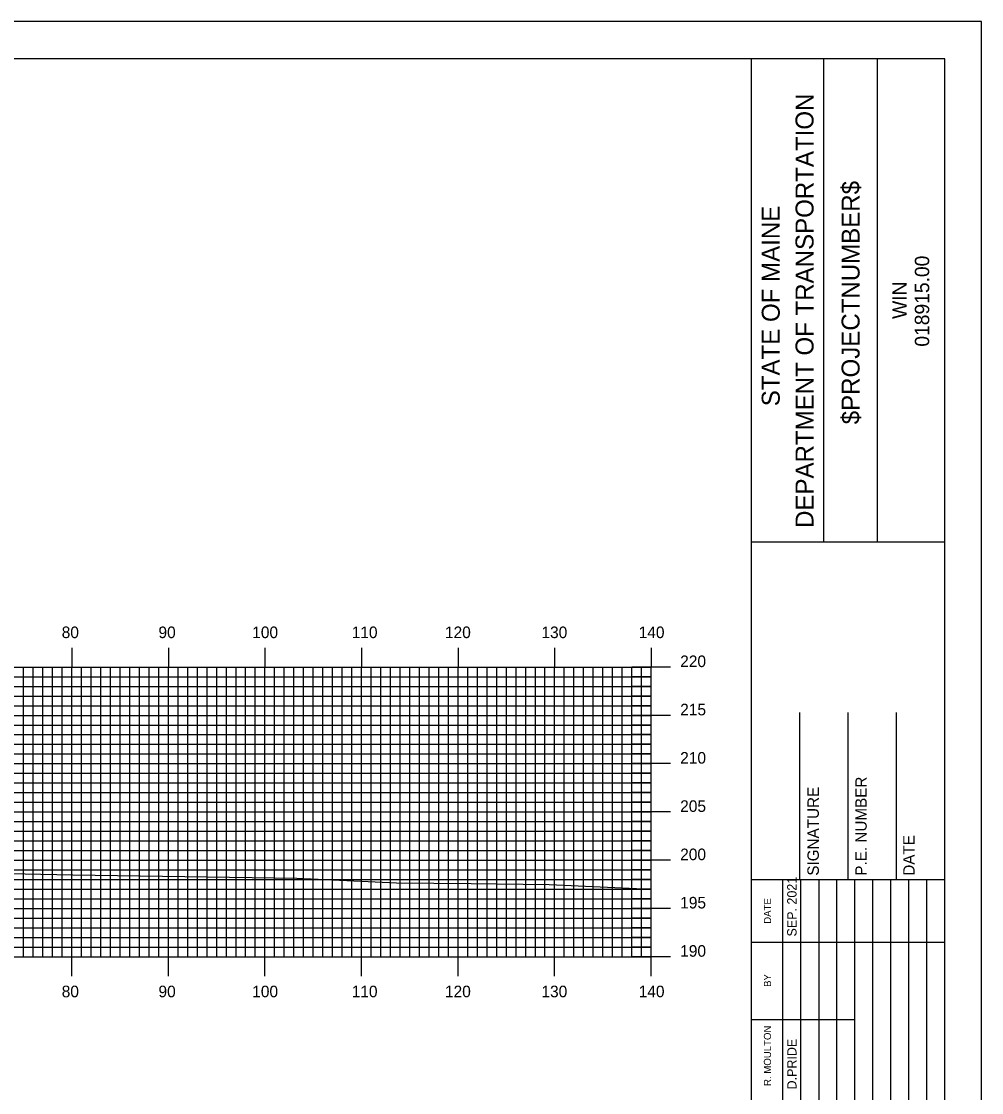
# Model space of a CAD drawing. Extents: x 1805864 to 1806208, y 442591 to 442811.
# Drawn here: x 1806105 to 1806204.4, y 442699.6 to 442810.5 of the extents above; entities that cross this region are included whole.
import ezdxf

# ---------------------------------------------------------------- set-up
doc = ezdxf.new("R2010")
doc.units = 0
for name, color, linetype in [('BORDER', 7, 'Continuous'), ('H_V ANNOTATION', 7, 'Continuous'), ('MAJOR', 7, 'Continuous'), ('MINOR', 7, 'Continuous'), ('PLOT BOUNDARY', 7, 'Continuous'), ('S_Roadway_Centerline', 7, 'Continuous')]:
    doc.layers.add(name, color=color, linetype=linetype)

msp = doc.modelspace()

# ---------------------------------------------------------------- linework, layer by layer
at = {"layer": 'BORDER'}
for p, q in [((1806180.62, 442596.67), (1806180.62, 442806.67)), ((1806188.08, 442756.66), (1806188.08, 442806.66)), ((1806193.67, 442756.66), (1806193.67, 442806.66)), ((1806180.62, 442756.65), (1806200.62, 442756.65)), ((1806185.62, 442721.67), (1806185.62, 442738.97)), ((1806190.62, 442721.67), (1806190.62, 442738.97)), ((1806195.62, 442721.67), (1806195.62, 442738.97)), ((1806180.62, 442721.67), (1806200.62, 442721.67))]:
    msp.add_line(p, q, dxfattribs=at)
msp.add_lwpolyline([(1805880.62, 442596.67), (1806200.62, 442596.67), (1806200.62, 442806.67), (1805880.62, 442806.67)], close=True, dxfattribs=at)
for points in [[(1806183.85, 442715.17), (1806183.85, 442721.67)], [(1806185.71, 442686.68), (1806185.71, 442721.67)], [(1806187.58, 442721.67), (1806187.58, 442686.68)], [(1806189.44, 442686.68), (1806189.44, 442721.67)], [(1806191.3, 442686.68), (1806191.3, 442721.67)], [(1806193.17, 442686.68), (1806193.17, 442721.67)], [(1806195.03, 442686.68), (1806195.03, 442721.67)], [(1806196.89, 442686.68), (1806196.89, 442721.67)], [(1806198.76, 442686.68), (1806198.76, 442721.67)], [(1806183.85, 442686.68), (1806183.85, 442720.26)], [(1806180.62, 442715.17), (1806200.62, 442715.17)], [(1806180.62, 442707.17), (1806183.85, 442707.17)], [(1806183.85, 442707.17), (1806191.3, 442707.17)]]:
    msp.add_lwpolyline(points, dxfattribs=at)
at = {"layer": 'MAJOR'}
for p, q in [((1806110.22, 442745.67), (1806110.22, 442743.67)), ((1806120.22, 442745.67), (1806120.22, 442743.67)), ((1806130.22, 442745.67), (1806130.22, 442743.67)), ((1806140.22, 442745.67), (1806140.22, 442743.67)), ((1806150.22, 442745.67), (1806150.22, 442743.67)), ((1806160.22, 442745.67), (1806160.22, 442743.67)), ((1806170.22, 442745.67), (1806170.22, 442743.67)), ((1805890.22, 442743.67), (1806170.22, 442743.67)), ((1805890.22, 442743.67), (1806170.22, 442743.67)), ((1806110.22, 442713.67), (1806110.22, 442743.67)), ((1806120.22, 442713.67), (1806120.22, 442743.67)), ((1806130.22, 442713.67), (1806130.22, 442743.67)), ((1806140.22, 442713.67), (1806140.22, 442743.67)), ((1806150.22, 442713.67), (1806150.22, 442743.67)), ((1806160.22, 442713.67), (1806160.22, 442743.67)), ((1806172.22, 442743.67), (1806168.22, 442743.67)), ((1806170.22, 442713.67), (1806170.22, 442743.67)), ((1806170.22, 442713.67), (1806170.22, 442743.67)), ((1805890.22, 442738.67), (1806170.22, 442738.67)), ((1806172.22, 442738.67), (1806168.22, 442738.67)), ((1805890.22, 442733.67), (1806170.22, 442733.67)), ((1806172.22, 442733.67), (1806168.22, 442733.67)), ((1805890.22, 442728.67), (1806170.22, 442728.67)), ((1806172.22, 442728.67), (1806168.22, 442728.67)), ((1805890.22, 442723.67), (1806170.22, 442723.67)), ((1806172.22, 442723.67), (1806168.22, 442723.67)), ((1805890.22, 442718.67), (1806170.22, 442718.67)), ((1806172.22, 442718.67), (1806168.22, 442718.67)), ((1805890.22, 442713.67), (1806170.22, 442713.67)), ((1805890.22, 442713.67), (1806170.22, 442713.67)), ((1806110.22, 442711.66), (1806110.22, 442713.67)), ((1806120.22, 442711.66), (1806120.22, 442713.67)), ((1806130.22, 442711.66), (1806130.22, 442713.67)), ((1806140.22, 442711.66), (1806140.22, 442713.67)), ((1806150.22, 442711.66), (1806150.22, 442713.67)), ((1806160.22, 442711.66), (1806160.22, 442713.67)), ((1806172.22, 442713.67), (1806168.22, 442713.67)), ((1806170.22, 442711.66), (1806170.22, 442713.67))]:
    msp.add_line(p, q, dxfattribs=at)
at = {"layer": 'MINOR'}
for p, q in [((1806105.22, 442713.67), (1806105.22, 442743.67)), ((1806106.22, 442713.67), (1806106.22, 442743.67)), ((1806107.22, 442713.67), (1806107.22, 442743.67)), ((1806108.22, 442713.67), (1806108.22, 442743.67)), ((1806109.22, 442713.67), (1806109.22, 442743.67)), ((1806111.22, 442713.67), (1806111.22, 442743.67)), ((1806112.22, 442713.67), (1806112.22, 442743.67)), ((1806113.22, 442713.67), (1806113.22, 442743.67)), ((1806114.22, 442713.67), (1806114.22, 442743.67)), ((1806115.22, 442713.67), (1806115.22, 442743.67)), ((1806116.22, 442713.67), (1806116.22, 442743.67)), ((1806117.22, 442713.67), (1806117.22, 442743.67)), ((1806118.22, 442713.67), (1806118.22, 442743.67)), ((1806119.22, 442713.67), (1806119.22, 442743.67)), ((1806121.22, 442713.67), (1806121.22, 442743.67)), ((1806122.22, 442713.67), (1806122.22, 442743.67)), ((1806123.22, 442713.67), (1806123.22, 442743.67)), ((1806124.22, 442713.67), (1806124.22, 442743.67)), ((1806125.22, 442713.67), (1806125.22, 442743.67)), ((1806126.22, 442713.67), (1806126.22, 442743.67)), ((1806127.22, 442713.67), (1806127.22, 442743.67)), ((1806128.22, 442713.67), (1806128.22, 442743.67)), ((1806129.22, 442713.67), (1806129.22, 442743.67)), ((1806131.22, 442713.67), (1806131.22, 442743.67)), ((1806132.22, 442713.67), (1806132.22, 442743.67)), ((1806133.22, 442713.67), (1806133.22, 442743.67)), ((1806134.22, 442713.67), (1806134.22, 442743.67)), ((1806135.22, 442713.67), (1806135.22, 442743.67)), ((1806136.22, 442713.67), (1806136.22, 442743.67)), ((1806137.22, 442713.67), (1806137.22, 442743.67)), ((1806138.22, 442713.67), (1806138.22, 442743.67)), ((1806139.22, 442713.67), (1806139.22, 442743.67)), ((1806141.22, 442713.67), (1806141.22, 442743.67)), ((1806142.22, 442713.67), (1806142.22, 442743.67)), ((1806143.22, 442713.67), (1806143.22, 442743.67)), ((1806144.22, 442713.67), (1806144.22, 442743.67)), ((1806145.22, 442713.67), (1806145.22, 442743.67)), ((1806146.22, 442713.67), (1806146.22, 442743.67)), ((1806147.22, 442713.67), (1806147.22, 442743.67)), ((1806148.22, 442713.67), (1806148.22, 442743.67)), ((1806149.22, 442713.67), (1806149.22, 442743.67)), ((1806151.22, 442713.67), (1806151.22, 442743.67)), ((1806152.22, 442713.67), (1806152.22, 442743.67)), ((1806153.22, 442713.67), (1806153.22, 442743.67)), ((1806154.22, 442713.67), (1806154.22, 442743.67)), ((1806155.22, 442713.67), (1806155.22, 442743.67)), ((1806156.22, 442713.67), (1806156.22, 442743.67)), ((1806157.22, 442713.67), (1806157.22, 442743.67)), ((1806158.22, 442713.67), (1806158.22, 442743.67)), ((1806159.22, 442713.67), (1806159.22, 442743.67)), ((1806161.22, 442713.67), (1806161.22, 442743.67)), ((1806162.22, 442713.67), (1806162.22, 442743.67)), ((1806163.22, 442713.67), (1806163.22, 442743.67)), ((1806164.22, 442713.67), (1806164.22, 442743.67)), ((1806165.22, 442713.67), (1806165.22, 442743.67)), ((1806166.22, 442713.67), (1806166.22, 442743.67)), ((1806167.22, 442713.67), (1806167.22, 442743.67)), ((1806168.22, 442713.67), (1806168.22, 442743.67)), ((1806169.22, 442713.67), (1806169.22, 442743.67)), ((1805890.22, 442742.67), (1806170.22, 442742.67)), ((1806170.22, 442742.67), (1806168.22, 442742.67)), ((1805890.22, 442741.67), (1806170.22, 442741.67)), ((1805890.22, 442740.67), (1806170.22, 442740.67)), ((1806170.22, 442741.67), (1806168.22, 442741.67)), ((1806170.22, 442740.67), (1806168.22, 442740.67)), ((1805890.22, 442739.67), (1806170.22, 442739.67)), ((1806170.22, 442739.67), (1806168.22, 442739.67)), ((1805890.22, 442737.67), (1806170.22, 442737.67)), ((1806170.22, 442737.67), (1806168.22, 442737.67)), ((1805890.22, 442736.67), (1806170.22, 442736.67)), ((1806170.22, 442736.67), (1806168.22, 442736.67)), ((1805890.22, 442735.67), (1806170.22, 442735.67)), ((1806170.22, 442735.67), (1806168.22, 442735.67)), ((1805890.22, 442734.67), (1806170.22, 442734.67)), ((1806170.22, 442734.67), (1806168.22, 442734.67)), ((1805890.22, 442732.67), (1806170.22, 442732.67)), ((1806170.22, 442732.67), (1806168.22, 442732.67)), ((1805890.22, 442731.67), (1806170.22, 442731.67)), ((1805890.22, 442730.67), (1806170.22, 442730.67)), ((1806170.22, 442731.67), (1806168.22, 442731.67)), ((1806170.22, 442730.67), (1806168.22, 442730.67)), ((1805890.22, 442729.67), (1806170.22, 442729.67)), ((1806170.22, 442729.67), (1806168.22, 442729.67)), ((1805890.22, 442727.67), (1806170.22, 442727.67)), ((1806170.22, 442727.67), (1806168.22, 442727.67)), ((1805890.22, 442726.67), (1806170.22, 442726.67)), ((1806170.22, 442726.67), (1806168.22, 442726.67)), ((1805890.22, 442725.67), (1806170.22, 442725.67)), ((1806170.22, 442725.67), (1806168.22, 442725.67)), ((1805890.22, 442724.67), (1806170.22, 442724.67)), ((1806170.22, 442724.67), (1806168.22, 442724.67)), ((1805890.22, 442722.67), (1806170.22, 442722.67)), ((1806170.22, 442722.67), (1806168.22, 442722.67)), ((1805890.22, 442721.67), (1806170.22, 442721.67)), ((1805890.22, 442720.67), (1806170.22, 442720.67)), ((1806170.22, 442721.67), (1806168.22, 442721.67)), ((1806170.22, 442720.67), (1806168.22, 442720.67)), ((1805890.22, 442719.67), (1806170.22, 442719.67)), ((1806170.22, 442719.67), (1806168.22, 442719.67)), ((1805890.22, 442717.67), (1806170.22, 442717.67)), ((1806170.22, 442717.67), (1806168.22, 442717.67)), ((1805890.22, 442716.67), (1806170.22, 442716.67)), ((1806170.22, 442716.67), (1806168.22, 442716.67)), ((1805890.22, 442715.67), (1806170.22, 442715.67)), ((1806170.22, 442715.67), (1806168.22, 442715.67)), ((1805890.22, 442714.67), (1806170.22, 442714.67)), ((1806170.22, 442714.67), (1806168.22, 442714.67))]:
    msp.add_line(p, q, dxfattribs=at)
at = {"layer": 'PLOT BOUNDARY'}
msp.add_lwpolyline([(1805864.43, 442590.55), (1806204.43, 442590.55), (1806204.43, 442810.55), (1805864.43, 442810.55)], close=True, dxfattribs=at)
at = {"layer": 'S_Roadway_Centerline'}
msp.add_lwpolyline([(1805974.38, 442726.39), (1805991.94, 442725.48), (1805996.54, 442725.64), (1806011.45, 442725.51), (1806017.05, 442725.32), (1806036.94, 442724.98), (1806037.8, 442724.96), (1806038.06, 442724.95), (1806058.86, 442723.96), (1806060.86, 442723.81), (1806063.38, 442723.72), (1806074.08, 442723.27), (1806089.83, 442722.76), (1806102.05, 442722.31), (1806110.33, 442722.16), (1806133.52, 442721.8), (1806143.84, 442721.33), (1806151.57, 442721.26), (1806159.64, 442721.15), (1806170.22, 442720.68)], dxfattribs=at)

# ---------------------------------------------------------------- texts
at = {"layer": 'BORDER'}
for s, height, p in [('DEPARTMENT OF TRANSPORTATION', 1.8635, (1806187.03, 442758.08)), ('$PROJECTNUMBER$', 1.8635, (1806191.8, 442768.82)), ('STATE OF MAINE', 1.8635, (1806183.53, 442770.69)), ('018915.00', 1.491, (1806199.01, 442776.86)), ('WIN', 1.491, (1806196.69, 442779.73)), ('P.E. NUMBER', 1.1811, (1806192.54, 442722.06)), ('SIGNATURE', 1.181, (1806187.58, 442722.06)), ('DATE', 1.181, (1806197.5, 442722.06)), ('SEP. 2021', 0.969, (1806185.27, 442715.76)), ('DATE', 0.743, (1806182.63, 442717.08)), ('BY', 0.743, (1806182.63, 442710.54)), ('R. MOULTON', 0.745, (1806182.63, 442700.28)), ('D.PRIDE', 0.969, (1806185.27, 442699.92))]:
    msp.add_text(s, height=height, rotation=90, dxfattribs=at).set_placement(p)
at = {"layer": 'H_V ANNOTATION'}
for s, p in [('80', (1806109.17, 442746.67)), ('90', (1806119.19, 442746.67)), ('100', (1806128.9, 442746.67)), ('110', (1806139.2, 442746.67)), ('120', (1806148.86, 442746.67)), ('130', (1806158.85, 442746.67)), ('140', (1806168.92, 442746.67)), ('220', (1806173.22, 442743.67)), ('215', (1806173.22, 442738.67)), ('210', (1806173.22, 442733.67)), ('205', (1806173.22, 442728.67)), ('200', (1806173.22, 442723.67)), ('195', (1806173.22, 442718.67)), ('190', (1806173.22, 442713.67)), ('80', (1806109.17, 442709.47)), ('90', (1806119.19, 442709.47)), ('100', (1806128.9, 442709.47)), ('110', (1806139.2, 442709.47)), ('120', (1806148.86, 442709.47)), ('130', (1806158.85, 442709.47)), ('140', (1806168.92, 442709.47))]:
    msp.add_text(s, height=1.2, dxfattribs=at).set_placement(p)

doc.saveas('drawing.dxf')
